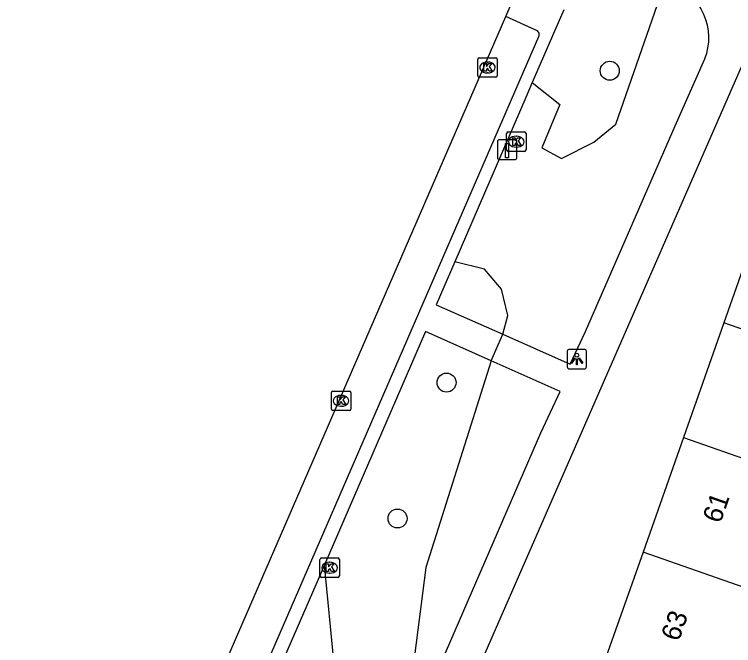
# Model space of a CAD drawing. Extents: x 163268 to 164360, y 381529 to 382285.
# Drawn here: x 163642.1 to 163679.15, y 381781.4 to 381813.93 of the extents above; entities that cross this region are included whole.
import ezdxf

# ---------------------------------------------------------------- set-up
doc = ezdxf.new("R2010")
doc.units = 0
for name, color, linetype in [('IMGEO_Boom', 7, 'Continuous'), ('IMGEO_Groenvoorziening', 7, 'Continuous'), ('IMGEO_Kolk', 7, 'Continuous'), ('IMGEO_Laadpaal', 7, 'Continuous'), ('IMGEO_Lichtpunt', 7, 'Continuous'), ('IMGEO_Pand', 7, 'Continuous'), ('IMGEO_Pand_nummerreeks', 7, 'Continuous'), ('IMGEO_Rijbaan_lokaal_open', 7, 'Continuous'), ('IMGEO_Voetpad_open', 7, 'Continuous')]:
    doc.layers.add(name, color=color, linetype=linetype)

msp = doc.modelspace()

# ---------------------------------------------------------------- linework, layer by layer
at = {"layer": 'IMGEO_Boom'}
for centre in [(163672.771, 381811.027), (163664.364, 381794.954), (163661.837, 381787.951)]:
    msp.add_circle(centre, 0.489, dxfattribs=at)
at = {"layer": 'IMGEO_Groenvoorziening'}
for points in [[(163668.78, 381810.415), (163670.194, 381809.286), (163669.274, 381807.048), (163670.285, 381806.507), (163671.945, 381807.337), (163673.083, 381808.276), (163675.631, 381815.598)], [(163667.255, 381797.445), (163667.523, 381798.42), (163667.198, 381799.774), (163666.314, 381800.803), (163664.786, 381801.179)], [(163666.67, 381796.073), (163663.299, 381785.424), (163662.541, 381779.539), (163659.472, 381776.615), (163658.462, 381777.229), (163658.57, 381780.442), (163658.074, 381785.559)]]:
    msp.add_lwpolyline(points, dxfattribs=at)
at = {"layer": 'IMGEO_Kolk'}
for p, q in [((163665.97, 381810.77), (163665.97, 381811.622)), ((163666.045, 381811.696), (163666.897, 381811.696)), ((163666.971, 381811.622), (163666.971, 381810.77)), ((163666.458, 381811.476), (163666.483, 381811.476)), ((163666.481, 381810.916), (163666.456, 381810.916)), ((163666.897, 381810.696), (163666.045, 381810.696)), ((163667.532, 381807.87), (163668.384, 381807.87)), ((163667.457, 381806.944), (163667.457, 381807.796)), ((163667.945, 381807.65), (163667.97, 381807.65)), ((163668.458, 381807.796), (163668.458, 381806.944)), ((163668.384, 381806.87), (163667.532, 381806.87)), ((163667.968, 381807.09), (163667.943, 381807.09)), ((163658.502, 381794.518), (163659.354, 381794.518)), ((163658.427, 381793.592), (163658.427, 381794.444)), ((163658.915, 381794.298), (163658.94, 381794.298)), ((163659.428, 381794.444), (163659.428, 381793.592)), ((163659.354, 381793.518), (163658.502, 381793.518)), ((163658.938, 381793.738), (163658.913, 381793.738)), ((163657.842, 381784.99), (163657.842, 381785.842)), ((163657.917, 381785.916), (163658.769, 381785.916)), ((163658.33, 381785.696), (163658.355, 381785.696)), ((163658.843, 381785.842), (163658.843, 381784.99)), ((163658.769, 381784.916), (163657.917, 381784.916)), ((163658.353, 381785.136), (163658.328, 381785.136))]:
    msp.add_line(p, q, dxfattribs=at)
for points in [[(163665.97, 381810.77), (163665.97, 381811.622)], [(163666.045, 381811.696), (163666.897, 381811.696)], [(163666.971, 381811.622), (163666.971, 381810.77)], [(163666.291, 381811.396), (163666.414, 381811.396), (163666.414, 381811.245), (163666.544, 381811.396), (163666.708, 381811.396), (163666.562, 381811.245), (163666.715, 381810.996), (163666.563, 381810.996), (163666.478, 381811.16), (163666.414, 381811.093), (163666.414, 381810.996), (163666.291, 381810.996), (163666.291, 381811.396)], [(163666.897, 381810.696), (163666.045, 381810.696)], [(163667.532, 381807.87), (163668.384, 381807.87)], [(163667.457, 381806.944), (163667.457, 381807.796)], [(163667.778, 381807.57), (163667.901, 381807.57), (163667.901, 381807.419), (163668.031, 381807.57), (163668.195, 381807.57), (163668.049, 381807.419), (163668.202, 381807.17), (163668.05, 381807.17), (163667.965, 381807.334), (163667.901, 381807.267), (163667.901, 381807.17), (163667.778, 381807.17), (163667.778, 381807.57)], [(163668.458, 381807.796), (163668.458, 381806.944)], [(163668.384, 381806.87), (163667.532, 381806.87)], [(163658.502, 381794.518), (163659.354, 381794.518)], [(163658.427, 381793.592), (163658.427, 381794.444)], [(163658.748, 381794.218), (163658.871, 381794.218), (163658.871, 381794.067), (163659.001, 381794.218), (163659.165, 381794.218), (163659.019, 381794.067), (163659.172, 381793.818), (163659.02, 381793.818), (163658.935, 381793.982), (163658.871, 381793.915), (163658.871, 381793.818), (163658.748, 381793.818), (163658.748, 381794.218)], [(163659.428, 381794.444), (163659.428, 381793.592)], [(163659.354, 381793.518), (163658.502, 381793.518)], [(163657.842, 381784.99), (163657.842, 381785.842)], [(163657.917, 381785.916), (163658.769, 381785.916)], [(163658.163, 381785.616), (163658.286, 381785.616), (163658.286, 381785.465), (163658.416, 381785.616), (163658.58, 381785.616), (163658.434, 381785.465), (163658.587, 381785.216), (163658.435, 381785.216), (163658.35, 381785.38), (163658.286, 381785.313), (163658.286, 381785.216), (163658.163, 381785.216), (163658.163, 381785.616)], [(163658.843, 381785.842), (163658.843, 381784.99)], [(163658.769, 381784.916), (163657.917, 381784.916)]]:
    msp.add_lwpolyline(points, dxfattribs=at)
for centre, start, end in [((163666.047, 381811.62), 91.552, 178.448), ((163666.047, 381811.62), 91.552, 178.448), ((163666.895, 381811.62), 1.552, 88.448), ((163666.895, 381811.62), 1.552, 88.448), ((163666.047, 381810.772), 181.552, 268.448), ((163666.047, 381810.772), 181.552, 268.448), ((163666.895, 381810.772), 271.552, 358.448), ((163666.895, 381810.772), 271.552, 358.448), ((163667.534, 381807.794), 91.552, 178.448), ((163667.534, 381807.794), 91.552, 178.448), ((163668.382, 381807.794), 1.552, 88.448), ((163668.382, 381807.794), 1.552, 88.448), ((163667.534, 381806.946), 181.552, 268.448), ((163667.534, 381806.946), 181.552, 268.448), ((163668.382, 381806.946), 271.552, 358.448), ((163668.382, 381806.946), 271.552, 358.448), ((163658.504, 381794.442), 91.552, 178.448), ((163658.504, 381794.442), 91.552, 178.448), ((163659.352, 381794.442), 1.552, 88.448), ((163659.352, 381794.442), 1.552, 88.448), ((163658.504, 381793.594), 181.552, 268.448), ((163658.504, 381793.594), 181.552, 268.448), ((163659.352, 381793.594), 271.552, 358.448), ((163659.352, 381793.594), 271.552, 358.448), ((163657.919, 381785.84), 91.552, 178.448), ((163657.919, 381785.84), 91.552, 178.448), ((163658.767, 381785.84), 1.552, 88.448), ((163658.767, 381785.84), 1.552, 88.448), ((163657.919, 381784.992), 181.552, 268.448), ((163657.919, 381784.992), 181.552, 268.448), ((163658.767, 381784.992), 271.552, 358.448), ((163658.767, 381784.992), 271.552, 358.448)]:
    msp.add_arc(centre, 0.0765, start, end, dxfattribs=at)
for centre, major_axis, ratio, start_param, end_param in [((163666.457, 381811.196), (-0.387, 0.002), 0.722429, 4.712389, 7.853982), ((163666.482, 381811.196), (-0.39, 0.002), 0.717154, 1.570796, 4.712389), ((163667.944, 381807.37), (-0.387, 0.002), 0.722429, 4.712389, 7.853982), ((163667.969, 381807.37), (-0.39, 0.002), 0.717154, 1.570796, 4.712389), ((163658.914, 381794.018), (-0.387, 0.002), 0.722429, 4.712389, 7.853982), ((163658.939, 381794.018), (-0.39, 0.002), 0.717154, 1.570796, 4.712389), ((163658.329, 381785.416), (-0.387, 0.002), 0.722429, 4.712389, 7.853982), ((163658.354, 381785.416), (-0.39, 0.002), 0.717154, 1.570796, 4.712389)]:
    msp.add_ellipse(centre, major_axis=major_axis, ratio=ratio, start_param=start_param, end_param=end_param, dxfattribs=at)
at = {"layer": 'IMGEO_Laadpaal'}
for p, q in [((163666.984, 381807.376), (163666.984, 381806.535)), ((163666.984, 381807.376), (163666.984, 381806.535)), ((163667.9, 381807.46), (163667.059, 381807.46)), ((163667.9, 381807.46), (163667.059, 381807.46)), ((163667.984, 381806.544), (163667.984, 381807.385)), ((163667.984, 381806.544), (163667.984, 381807.385)), ((163667.068, 381806.46), (163667.909, 381806.46)), ((163667.068, 381806.46), (163667.909, 381806.46))]:
    msp.add_line(p, q, dxfattribs=at)
msp.add_lwpolyline([(163667.399, 381807.273), (163667.559, 381807.273), (163667.559, 381806.54), (163667.399, 381806.54), (163667.399, 381807.273)], dxfattribs=at)
for centre, start, end in [((163667.062, 381807.382), 92.4484, 184.2845), ((163667.062, 381807.382), 92.4484, 184.2845), ((163667.906, 381807.382), 2.4484, 94.2845), ((163667.906, 381807.382), 2.4484, 94.2845), ((163667.062, 381806.538), 182.4484, 274.2845), ((163667.062, 381806.538), 182.4484, 274.2845), ((163667.906, 381806.538), 272.4484, 4.2845), ((163667.906, 381806.538), 272.4484, 4.2845)]:
    msp.add_arc(centre, 0.0779, start, end, dxfattribs=at)
at = {"layer": 'IMGEO_Lichtpunt'}
for p, q in [((163670.578, 381796.57), (163670.578, 381795.763)), ((163670.578, 381796.57), (163670.578, 381795.763)), ((163671.48, 381796.665), (163670.672, 381796.665)), ((163671.48, 381796.665), (163670.672, 381796.665)), ((163671.574, 381795.763), (163671.574, 381796.57)), ((163671.574, 381795.763), (163671.574, 381796.57)), ((163670.672, 381795.669), (163671.48, 381795.669)), ((163670.672, 381795.669), (163671.48, 381795.669))]:
    msp.add_line(p, q, dxfattribs=at)
for points in [[(163670.952, 381796.234), (163670.991, 381796.206), (163670.803, 381795.944), (163670.765, 381795.971), (163670.952, 381796.234)], [(163671.054, 381796.186), (163671.101, 381796.186), (163671.101, 381795.864), (163671.054, 381795.864), (163671.054, 381796.186)], [(163671.164, 381796.206), (163671.202, 381796.233), (163671.389, 381795.971), (163671.35, 381795.943), (163671.164, 381796.206)]]:
    msp.add_lwpolyline(points, dxfattribs=at)
msp.add_circle((163671.077, 381796.368), 0.0994, dxfattribs=at)
for centre, start, end in [((163670.672, 381796.57), 90, 180), ((163670.672, 381796.57), 90, 180), ((163671.48, 381796.57), 0, 90), ((163671.48, 381796.57), 0, 90), ((163670.672, 381795.763), 180, 270), ((163670.672, 381795.763), 180, 270), ((163671.48, 381795.763), 270, 0), ((163671.48, 381795.763), 270, 360)]:
    msp.add_arc(centre, 0.0946, start, end, dxfattribs=at)
at = {"layer": 'IMGEO_Pand'}
for points in [[(163683.186, 381803.942), (163681.001, 381804.712), (163678.652, 381798.043)], [(163678.652, 381798.043), (163676.569, 381792.13)], [(163686.959, 381795.132), (163678.652, 381798.043)], [(163676.569, 381792.13), (163674.486, 381786.216)], [(163676.569, 381792.13), (163684.876, 381789.218)], [(163674.486, 381786.216), (163672.403, 381780.302)], [(163682.793, 381783.305), (163674.486, 381786.216)]]:
    msp.add_lwpolyline(points, dxfattribs=at)
at = {"layer": 'IMGEO_Rijbaan_lokaal_open'}
for points in [[(163667.414, 381813.825), (163667.695, 381814.465)], [(163642.095, 381755.459), (163667.414, 381813.825)]]:
    msp.add_lwpolyline(points, dxfattribs=at)
at = {"layer": 'IMGEO_Voetpad_open'}
for points in [[(163670.398, 381814.16), (163668.78, 381810.415)], [(163668.962, 381813.124), (163667.414, 381813.825)], [(163644.035, 381754.962), (163669.114, 381812.797)], [(163653.198, 381750), (163653.323, 381751.193), (163679.851, 381811.893)], [(163667.255, 381797.445), (163670.736, 381795.905), (163671.522, 381797.593), (163676.148, 381808.181), (163677.678, 381811.648)], [(163668.78, 381810.415), (163668.449, 381809.65), (163664.786, 381801.179)], [(163664.786, 381801.179), (163663.828, 381798.962), (163667.255, 381797.445)], [(163666.67, 381796.073), (163663.271, 381797.586), (163658.074, 381785.559)], [(163666.67, 381796.073), (163667.255, 381797.445)], [(163651.958, 381771.509), (163658.866, 381768.438), (163661.227, 381773.927), (163669.214, 381792.364), (163670.212, 381794.497), (163666.67, 381796.073)], [(163658.074, 381785.559), (163657.922, 381785.206), (163651.958, 381771.509)]]:
    msp.add_lwpolyline(points, dxfattribs=at)
for centre, radius, start, end in [((163674.914, 381812.715), 2.963, 338.8846, 69.4742), ((163668.892, 381812.893), 0.242, 336.7507, 73.1103)]:
    msp.add_arc(centre, radius, start, end, dxfattribs=at)

# ---------------------------------------------------------------- texts
at = {"layer": 'IMGEO_Pand_nummerreeks'}
for s, p in [('61', (163678.47, 381787.655)), ('63', (163676.327, 381781.571))]:
    msp.add_text(s, height=1, rotation=70.5954, dxfattribs=at).set_placement(p)

doc.saveas('drawing.dxf')
